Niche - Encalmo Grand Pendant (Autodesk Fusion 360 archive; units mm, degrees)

design "Encalmo Grand" references "Luxe Single Pendant Cordset - 4ft Standard", "Niche - Chief Architect - Luxe Single Pendant Cordset", "Encalmo Grand"
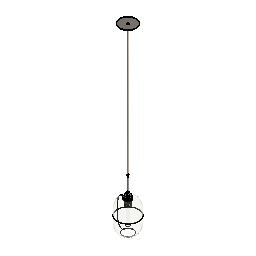
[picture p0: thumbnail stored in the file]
external_derived "ExternalDerived1" bodies "Encalmo Grand", "Encalmo Grand (1)"
external_derived "ExternalDerived2" bodies "Socket Body", "Shade Ring", "Shade Ring +Collar", "Socket", "Body1", "Metal Strain Relief", "Fabric Cord (1)", "Stem (Threaded)"
move "Move1"
external_derived "ExternalDerived3" bodies "T9-Bulb"
move "Move2"
scale "Scale1"
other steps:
derived_base_feature "Derived Base Feature1" bodies "Encalmo Grand", "Encalmo Grand (1)"
derived_base_feature "Derived Base Feature2" bodies "Socket Body", "Shade Ring", "Shade Ring +Collar", "Socket", "Body1", "Metal Strain Relief", "Fabric Cord (1)", "Stem (Threaded)"
derived_base_feature "Derived Base Feature3" bodies "T9-Bulb"
named bodies: "Encalmo Grand", "Encalmo Grand (1)", "Socket Body", "Shade Ring", "Shade Ring +Collar", "Socket", "Body1", "Metal Strain Relief", "Fabric Cord (1)", "Stem (Threaded)", "Cap (Threaded)", "5M Set Screw", "T9-Bulb"

design "Luxe Single Pendant Cordset - 4ft Standard" references "Luxe Canopy - Single Pendant Cordset"
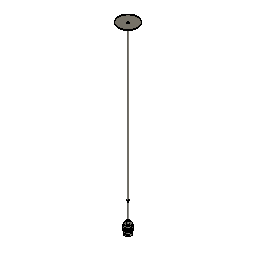
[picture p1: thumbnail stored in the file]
external_derived "ExternalDerived2" bodies "Cap (Threaded)"
move "Move1"
move "Move2"
offset_faces "OffsetFaces1" distance 1051.56
move "Move3"
move "Move4"
move "Move5"
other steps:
derived_base_feature "Derived Base Feature9" bodies "Socket Body", "Shade Ring", "Shade Ring +Collar", "Socket"
derived_base_feature "Derived Base Feature10" bodies "Body1"
derived_base_feature "Derived Base Feature12" bodies "Metal Strain Relief"
derived_base_feature "Derived Base Feature13" bodies "Fabric Cord (1)"
derived_base_feature "Derived Base Feature14" bodies "Stem (Threaded)"
derived_base_feature "Derived Base Feature15" bodies "Cap 9Threaded)", "Cap (Threaded)"
named bodies: "Socket Body", "Shade Ring", "Shade Ring +Collar", "Socket", "Metal Strain Relief", "Fabric Cord (1)", "Stem (Threaded)", "Cap 9Threaded)", "Body1", "Cap (Threaded)", "5M Set Screw"

design "Encalmo Grand" references "Niche_Encalmo_Grand_Single_Pendant"
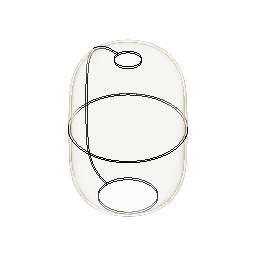
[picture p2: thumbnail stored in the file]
external_derived "ExternalDerived1" bodies "Encalmo Grand"
work_plane "WorkPlane1" AlongDistance -124.2212
split "Split1" bodies "Encalmo Grand (1)"
fillet "Fillet1" radius 0.0254
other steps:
derived_base_feature "Derived Base Feature" bodies "Encalmo Grand"
named bodies: "Encalmo Grand", "Encalmo Grand (1)"

design "Luxe Canopy - Single Pendant Cordset" references "Luxe Cordset", "M5 Set Screw", "Canopy Mounting Bar", "Plastic Strain Relief", "Canopy Mounting Bar Screw"
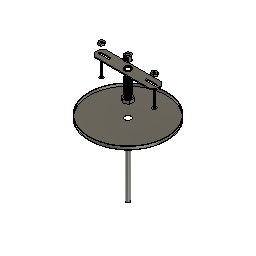
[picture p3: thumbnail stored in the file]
sketch "Sketch1" plane through (0, 0, 0) normal (0, 0, 1) x axis (1, 0, 0)
  circle C1 centre (0, 0) radius 63.5
  point P1 (0, 0)
  point P2 (0, 0)
  coincident P1 P2
  dimension "d1" diameter C1 = 127
extrude "Extrude1" new body sketch "Sketch1" along normal blind 5.08
shell "Shell1" innerThickness 0.762
hole "Hole1" HoleDepth 35.56 HoleDiameter 10.16 TipAngle 118
component_from_bodies "Body->Comp1"
component_insert "Component Insert1"
component_insert "Component Insert2"
component_insert "Component Insert3"
sketch "Sketch2" plane through (0, 0, 0) normal (0, 0, 1) x axis (1, 0, 0)
  circle C1 centre (0, 0) radius 3.175
  point P1 (0, 0)
  point P2 (0, 0)
  coincident P1 P2
  dimension "d8" diameter C1 = 6.35
extrude "Extrude2" new body sketch "Sketch2" along normal blind 127 and against normal blind 127 bodies "Fabric Cord"
component_insert "Component Insert4"
component_insert "Component Insert5"
position "Position1"
sketch "Sketch3" plane through (0, 0, 0.762) normal (0, 0, 1) x axis (-1, 0, 0)
  circle C1 centre (-0.0475, 0.2257) radius 5.08
  circle C2 centre (0, 0) radius 62.738
  circle C3 centre (0, 0) radius 4.826
  concentric C2 C3
  dimension "d13" diameter C3 = 9.652
extrude "Extrude3" new body sketch "Sketch3" profile of C3 along normal blind 25.4 bodies "Threaded Nipple"
shell "Shell2" innerThickness 1.27
thread "Thread1"
sketch "Sketch5" plane through (0, 0, 127) normal (0, 0, 1) x axis (-1, 0, 0)
  line L1 (-6.8191, 3.937) -> (0, 7.874)
  line L2 (-6.8191, -3.937) -> (-6.8191, 3.937)
  line L3 (0, -7.874) -> (-6.8191, -3.937)
  line L4 (6.8191, -3.937) -> (0, -7.874)
  line L5 (6.8191, 3.937) -> (6.8191, -3.937)
  line L6 (0, 7.874) -> (6.8191, 3.937)
  circle C1 centre (0, 0) radius 3.175
  point P2 (0, 0)
  point P9 (0, 0)
  point P3 (0, 7.874)
  coincident P2 P9
  dimension "d20" distance P3 P9 = 7.874
extrude "Extrude4" new body sketch "Sketch5" along normal blind 5.08 bodies "Hex Nut"
move "Move1"
thread "Thread2"
move "Move2" TranslateX 0 TranslateY 0 TranslateZ -55.88
move "Move3" TranslateX 0 TranslateY 0 TranslateZ 60.96
position "Position2"
sketch "Sketch6" plane through (0, 0, 0) normal (0, 0, 1) x axis (1, 0, 0)
  circle C1 centre (0, 0) radius 9.525
  point P1 (0, 0)
  point P2 (0, 0)
  coincident P1 P2
  dimension "d29" diameter C1 = 19.05
extrude "Extrude5" new body sketch "Sketch6" along normal blind 16.129 bodies "Metal Strain Relief"
move "Move4" TranslateX 0 TranslateY 0 TranslateZ -86.36
hole "Hole2" HoleDepth 10.16 HoleDiameter 5.08 TipAngle 118
hole "Hole3" HoleDepth 4.064 HoleDiameter 7.62 TipAngle 180
hole "Hole4" HoleDepth 12.192 HoleDiameter 9.144 TipAngle 180
thread "Thread3" ThreadOffset 0 ThreadLength 6.096
move "Move1" TranslateX 0 TranslateY 0 TranslateZ 68.58
move "Move5" TranslateX 0 TranslateY 0 TranslateZ 138.43
component_insert "Component Insert6"
external_derived "ExternalDerived1" bodies "5M Set Screw"
move "Move6" TranslateX 0 TranslateY 0 TranslateZ -185.42
copy_paste_bodies "CopyPasteBodies1"
move "Move7" TranslateX 0 TranslateY 0 TranslateZ -12.7
offset_faces "OffsetFaces1" distance -152.4
move "Move8"
component_from_bodies "Body->Comp2"
component_from_bodies "Body->Comp3"
component_from_bodies "Body->Comp4"
component_from_bodies "Body->Comp5"
hole "Hole1" HoleDepth 25.4 HoleDiameter 6.35 TipAngle 180
sketch "Sketch7" plane through (0, 0, 0) normal (0, 0, 1) x axis (1, 0, 0)
  line L1 (49.784, 3.9595) -> (52.07, 0)
  line L2 (45.212, 3.9595) -> (49.784, 3.9595)
  line L3 (42.926, 0) -> (45.212, 3.9595)
  line L4 (45.212, -3.9595) -> (42.926, 0)
  line L5 (49.784, -3.9595) -> (45.212, -3.9595)
  line L6 (52.07, 0) -> (49.784, -3.9595)
  point P2 (52.07, 0)
  point P8 (47.498, 0)
  dimension "d63" distance P2 P8 = 4.572
extrude "Extrude6" new body sketch "Sketch7" along normal blind 3.175 bodies "Mounting Hex Nut"
hole "Hole5" HoleDepth 25.4 HoleDiameter 3.81 TipAngle 180
thread "Thread4"
move "Move9"
component_from_bodies "Body->Comp6"
copy_paste "CopyPaste1"
move "Move10"
derived_base_feature "Derived Base Feature3" bodies "Stem (Threaded)", "Cap 9Threaded)"
move "Move11"
component_from_bodies "Body->Comp7"
component_from_bodies "Body->Comp8"
component_from_bodies "Body->Comp9"
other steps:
base_feature "Base Feature1"
base_feature "Base Feature1" bodies "Stem (Threaded)"
base_feature "Base Feature1" bodies "Cap 9Threaded)"
base_feature "Base Feature1" bodies "Fabric Cord"
base_feature "Base Feature1" bodies "Metal Strain Relief"
base_feature "Base Feature1" bodies "Mounting Hex Nut"
base_feature "Base Feature1" bodies "Hex Nut"
base_feature "Base Feature1" bodies "Fabric Cord (1)"
base_feature "Base Feature1" bodies "Threaded Nipple"
derived_base_feature "Derived Base Feature1" bodies "Socket Body", "Shade Ring", "Shade Ring +Collar", "Socket", "Rigid Stem"
derived_base_feature "Derived Base Feature2" bodies "5M Set Screw"
base_feature "Base Feature1" bodies "Fabric Cord", "Fabric Cord (1)"
create_component "CreateComponent1"
remove_body "RemoveBody1"
create_component "CreateComponent2"
remove_body "RemoveBody2"
create_component "CreateComponent3"
remove_body "RemoveBody3"
create_component "CreateComponent4"
remove_body "RemoveBody4"
create_component "CreateComponent5"
remove_body "RemoveBody5"
create_component "CreateComponent6"
remove_body "RemoveBody6"
create_component "CreateComponent7"
remove_body "RemoveBody7"
create_component "CreateComponent8"
remove_body "RemoveBody8"
create_component "CreateComponent9"
remove_body "RemoveBody9"
named bodies: "Fabric Cord", "Threaded Nipple", "Hex Nut", "Metal Strain Relief", "Socket Body", "Shade Ring", "Shade Ring +Collar", "Socket", "Rigid Stem", "5M Set Screw", "Fabric Cord (1)", "Mounting Hex Nut", "Stem (Threaded)", "Cap 9Threaded)"

design "Niche - Chief Architect - Luxe Single Pendant Cordset"
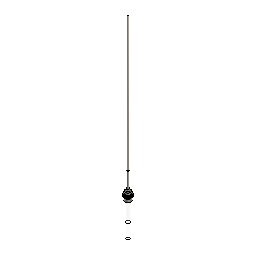
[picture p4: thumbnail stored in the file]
derived_base_feature "Derived Base Feature" bodies "Socket Body", "Shade Ring", "Shade Ring +Collar", "Socket", "Canopy", "Metal Strain Relief", "Fabric Cord (1)", "Stem (Threaded)"
remove_body "RemoveBody1"
remove_body "RemoveBody2"
split "Split1" bodies "Socket Body (1)"
remove_body "RemoveBody3"
align "Align1"
hole "Hole1" HoleDepth 19.05 HoleDiameter 8.89 TipAngle 118
combine "Combine1" bodies "Shade Ring"
split "Split2" bodies "Socket (1)"
remove_body "RemoveBody4"
split "Split3" bodies "Fabric Cord (1) (1)"
remove_body "RemoveBody5"
combine "Combine2" bodies "Socket Body"
align "Align2"
combine "Combine3" bodies "Metal Strain Relief"
sketch "Sketch1" plane through (0, 0, 0) normal (0, 1, 0) x axis (1, 0, 0)
  line L1 (13.1098, 24.9049) -> (-12.2902, 24.9049)
  line L2 (18.1898, 37.1766) -> (18.1898, 29.9849)
  line L3 (-17.3702, 29.9849) -> (-17.3702, 36.7132)
  line L4 (0, 132.969) -> (0, 24.9049)
  arc A1 centre (0, 86.36) radius 46.609 clockwise from (-22.6031, 45.5985) to (23.276, 45.979)
  arc A2 centre (-27.5302, 36.7132) radius 10.16 clockwise from (-22.6031, 45.5985) to (-17.3702, 36.7132)
  arc A3 centre (28.3498, 37.1766) radius 10.16 clockwise from (18.1898, 37.1766) to (23.276, 45.979)
  arc A4 centre (-12.2902, 29.9849) radius 5.08 clockwise from (-12.2902, 24.9049) to (-17.3702, 29.9849)
  arc A5 centre (13.1098, 29.9849) radius 5.08 clockwise from (18.1898, 29.9849) to (13.1098, 24.9049)
  point P5 (18.1898, 43.4469)
  point P3 (-17.3702, 24.9049)
  point P4 (18.1898, 24.9049)
  point P18 (0, 24.9049)
  point P19 (0, 132.969)
  horizontal L1
  vertical L2
  vertical L3
  tangent A1 A2
  tangent L3 A2
  coincident P5 L2
  coincident P5 A1
  tangent L2 A3
  tangent A1 A3
  equal A2 A3
  coincident P3 L1
  coincident P3 L3
  tangent L1 A4
  tangent L3 A4
  coincident P4 L1
  coincident P4 L2
  tangent L1 A5
  tangent L2 A5
  coincident L1 P18
  coincident A1 P19
  perpendicular L1 L4
  dimension "d4" diameter A1 = 93.218
  dimension "d5" distance P3 P4 = 35.56
  dimension "d6" distance P4 P5 = 18.542
  dimension "d7" radius A2 = 10.16
  dimension "d8" radius A4 = 5.08
  dimension "d9" radius A5 = 5.08
revolve "Revolve1" sketch "Sketch1" AlongAngle 360 bodies "G30-Bulb"
move "Move1"
sketch "Sketch2" plane through (0, 0, 0) normal (0, 1, 0) x axis (1, 0, 0)
  line L1 (12.7, 0) -> (-12.7, 0)
  line L2 (12.7, 152.4) -> (12.7, 0)
  line L3 (-12.7, 0) -> (-12.7, 152.4)
  line L4 (0, 165.1) -> (0, 0)
  arc A1 centre (0, 152.4) radius 12.7 clockwise from (-12.7, 152.4) to (12.7, 152.4)
  point P1 (0, 0)
  point P7 (0, 0)
  point P8 (0, 165.1)
  horizontal L1
  vertical L2
  vertical L3
  coincident P1 P7
  midpoint A1 P8
  perpendicular L1 L4
revolve "Revolve2" sketch "Sketch2" AlongAngle 360 bodies "T9-Bulb"
move "Move2"
sketch "Sketch3" plane through (0, 0, 0) normal (0, 1, 0) x axis (1, 0, 0)
  line L1 (12.7, 0) -> (-12.7, 0)
  line L2 (12.7, 254) -> (12.7, 0)
  line L3 (-12.7, 0) -> (-12.7, 254)
  line L4 (0, 266.7) -> (0, 0)
  arc A1 centre (0, 254) radius 12.7 clockwise from (-12.7, 254) to (12.7, 254)
  point P1 (0, 0)
  point P7 (0, 0)
  point P8 (0, 266.7)
  horizontal L1
  vertical L2
  vertical L3
  coincident P1 P7
  midpoint A1 P8
  perpendicular L1 L4
revolve "Revolve3" sketch "Sketch3" AlongAngle 360 bodies "T8-Bulb"
move "Move3"
move "Move4"
move "Move5"
sketch "Sketch4" plane through (0, 0, 0) normal (0, 1, 0) x axis (1, 0, 0)
  line L1 (15.875, -8.763) -> (-15.875, -8.763)
  line L2 (15.875, 22.987) -> (15.875, -8.763)
  line L3 (-15.875, 22.987) -> (15.875, 22.987)
  line L4 (-15.875, -8.763) -> (-15.875, 22.987)
  line L5 (0, 22.987) -> (0, -8.763)
  point P6 (0, -8.763)
  point P7 (0, 22.987)
  point P2 (-15.875, -8.763)
  point P3 (15.875, -8.763)
  point P5 (-15.875, 22.987)
  horizontal L1
  vertical L2
  horizontal L3
  vertical L4
  midpoint L1 P6
  midpoint L3 P7
  dimension "d13" distance P2 P3 = 31.75
  dimension "d14" distance P2 P5 = 31.75
revolve "Revolve4" sketch "Sketch4" AlongAngle 360 bodies "Bulb Extender"
move "Move6"
sketch "Sketch5" plane through (0, 0, 0) normal (0, 1, 0) x axis (1, 0, 0)
  line L1 (-12.7, 35.56) -> (12.7, 35.56)
  line L2 (-12.7, 5.08) -> (-12.7, 35.56)
  line L3 (12.7, 5.08) -> (-12.7, 5.08)
  line L4 (12.7, 35.56) -> (12.7, 5.08)
  line L5 (-12.7, 5.08) -> (12.7, 35.56)
  line L6 (12.7, 5.08) -> (-12.7, 35.56)
  line L7 (0, 35.56) -> (0, 5.08)
  point P6 (0, 20.32)
  point P7 (0, 5.08)
  point P8 (0, 35.56)
  horizontal L1
  perpendicular L1 L2
  parallel L1 L3
  parallel L2 L4
  coincident L5 P6
  coincident L6 P6
  midpoint L3 P7
  midpoint L1 P8
revolve "Revolve5" sketch "Sketch5" AlongAngle 360 bodies "Y-Spliter"
sketch "Sketch6" plane through (0, 0, 0) normal (0, 1, 0) x axis (1, 0, 0)
  line L1 (-55.88, 64.9514) -> (-21.59, 64.9514)
  line L2 (-55.88, 35.7414) -> (-55.88, 64.9514)
  line L3 (-21.59, 35.7414) -> (-55.88, 35.7414)
  line L4 (-21.59, 64.9514) -> (-21.59, 35.7414)
  line L5 (-55.88, 35.7414) -> (-21.59, 64.9514)
  line L6 (-21.59, 35.7414) -> (-55.88, 64.9514)
  line L7 (-38.735, 64.9514) -> (-38.735, 35.7414)
  point P6 (-38.735, 50.3464)
  point P7 (-38.735, 35.7414)
  point P8 (-38.735, 64.9514)
  point P4 (-55.88, 35.7414)
  point P5 (-21.59, 35.7414)
  point P2 (-21.59, 64.9514)
  horizontal L1
  perpendicular L1 L2
  parallel L1 L3
  parallel L2 L4
  coincident L5 P6
  coincident L6 P6
  midpoint L3 P7
  midpoint L1 P8
  dimension "d17" distance P4 P5 = 34.29
  dimension "d18" distance P2 P5 = 29.21
revolve "Revolve6" sketch "Sketch6" AlongAngle 360
chamfer "Chamfer1" distance 7.62
move "Move7"
mirror "Mirror1" mirrorStitchTolerance 0.1016
move "Move8"
combine "Combine4"
move "Move9"
sketch "Sketch7" plane through (0, 0, 0) normal (0, 1, 0) x axis (1, 0, 0)
  line L1 (-15.24, 40.64) -> (-15.24, 48.1816)
  line L2 (12.7, 38.1) -> (-12.7, 38.1)
  line L3 (15.24, 48.1816) -> (15.24, 40.64)
  line L4 (0, 100.1623) -> (0, 38.1)
  arc A1 centre (0, 76.2) radius 23.9623 clockwise from (-19.7282, 62.5988) to (19.7282, 62.5988)
  arc A2 centre (-40.64, 48.1816) radius 25.4 clockwise from (-19.7282, 62.5988) to (-15.24, 48.1816)
  arc A3 centre (40.64, 48.1816) radius 25.4 clockwise from (15.24, 48.1816) to (19.7282, 62.5988)
  arc A4 centre (-12.7, 40.64) radius 2.54 clockwise from (-12.7, 38.1) to (-15.24, 40.64)
  arc A5 centre (12.7, 40.64) radius 2.54 clockwise from (15.24, 40.64) to (12.7, 38.1)
  point P15 (0, 38.1)
  point P16 (0, 100.1623)
  parallel L1 L3
  tangent A1 A2
  tangent L1 A2
  tangent A1 A3
  tangent L3 A3
  tangent L1 A4
  tangent L2 A4
  tangent L2 A5
  tangent L3 A5
  midpoint L2 P15
  midpoint A1 P16
  perpendicular L2 L4
  dimension "d23" radius A2 = 25.4
  dimension "d24" radius A3 = 25.4
  dimension "d25" radius A4 = 2.54
  dimension "d26" radius A5 = 2.54
revolve "Revolve7" sketch "Sketch7" AlongAngle 360 bodies "A15-Bulb"
move "Move10"
copy_paste_bodies "CopyPasteBodies1"
copy_paste_bodies "CopyPasteBodies2"
move "Move11"
mirror "Mirror2" mirrorStitchTolerance 0.1016 bodies "A15-Bulb (1) (1)"
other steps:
base_feature "Base Feature1" bodies "Y-Spliter", "Bulb Extender", "Y-Spliter (1)", "Bulb Extender (1)"
base_feature "Base Feature2" bodies "A15-Bulb", "A15-Bulb (1)"
named bodies: "Socket Body", "Shade Ring", "Shade Ring +Collar", "Socket", "Canopy", "Metal Strain Relief", "Fabric Cord (1)", "Stem (Threaded)", "Adapter", "5M Set Screw", "Body1 (1)", "Socket Body (1)", "Socket (1)", "Fabric Cord (1) (1)", "G30-Bulb", "T9-Bulb", "T8-Bulb", "Bulb Extender", "Y-Spliter", "A15-Bulb", "Y-Spliter (1)", "Bulb Extender (1)", "A15-Bulb (1)", "A15-Bulb (1) (1)"

design "M5 Set Screw"
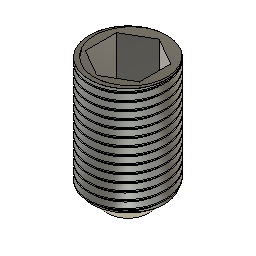
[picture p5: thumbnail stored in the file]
sketch "Sketch1" plane through (0, 0, 0) normal (0, 0, 1) x axis (1, 0, 0)
  circle C1 centre (0, 0) radius 2.5
  point P1 (0, 0)
  point P2 (0, 0)
  coincident P1 P2
  dimension "d1" diameter C1 = 5
extrude "Extrude1" new body sketch "Sketch1" along normal blind 8
sketch "Sketch2" plane through (0, 0, 8) normal (0, 0, 1) x axis (-1, 0, 0)
  line L1 (-1.7321, 1) -> (0, 2)
  line L2 (-1.7321, -1) -> (-1.7321, 1)
  line L3 (0, -2) -> (-1.7321, -1)
  line L4 (1.7321, -1) -> (0, -2)
  line L5 (1.7321, 1) -> (1.7321, -1)
  line L6 (0, 2) -> (1.7321, 1)
  circle C1 centre (0, 0) radius 2.5
  point P2 (0, 0)
  point P9 (0, 0)
  coincident P2 P9
extrude "Extrude2" cut sketch "Sketch2" profile of L1 L2 L3 L4 L5 L6 against normal blind 3
thread "Thread1" ThreadOffset 0.99 ThreadLength 7
chamfer "Chamfer1" distance 1.15

design "Luxe Cordset" references "M5 Set Screw"
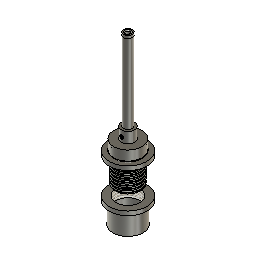
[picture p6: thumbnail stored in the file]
sketch "Sketch1" plane through (0, 0, 0) normal (0, 0, 1) x axis (1, 0, 0)
  circle C1 centre (0, 0) radius 20.6
  point P1 (0, 0)
  point P2 (0, 0)
  coincident P1 P2
  dimension "d11" diameter C1 = 41.2
extrude "Extrude1" new body sketch "Sketch1" along normal blind 14 bodies "Socket Body"
sketch "Sketch2" plane through (0, 0, 14) normal (0, 0, 1) x axis (-1, 0, 0)
  circle C1 centre (0, 0) radius 20.6
  circle C2 centre (0, 0) radius 9.6
  concentric C1 C2
  dimension "d3" diameter C2 = 19.2
extrude "Extrude2" add sketch "Sketch2" profile of C2 along normal blind 15.75
sketch "Sketch3" plane through (0, 0, 29.75) normal (0, 0, 1) x axis (-1, 0, 0)
  circle C1 centre (0, 0) radius 9.6
  circle C2 centre (0, 0) radius 5.75
  concentric C1 C2
  dimension "d6" diameter C2 = 11.5
extrude "Extrude3" new body sketch "Sketch3" profile of C2 along normal blind 114 bodies "Rigid Stem"
move "Move1"
sketch "Sketch4" plane through (0, 0, 203.75) normal (0, 0, 1) x axis (-1, 0, 0)
  circle C1 centre (0, 0) radius 5.75
  circle C2 centre (0, 0) radius 27.5
  dimension "d10" diameter C2 = 55
extrude "Extrude4" new body sketch "Sketch4" profile of C2 along normal blind 6 bodies "Shade Ring"
hole "Hole1" HoleDepth 25 HoleDiameter 42.75 TipAngle 118
sketch "Sketch5" plane through (0, 0, 0) normal (0, 0, 1) x axis (1, 0, 0)
  circle C1 centre (0, 0) radius 22
  point P1 (0, 0)
  point P2 (0, 0)
  coincident P1 P2
  dimension "d18" diameter C1 = 44
move "Move2"
copy_paste_bodies "CopyPasteBodies1"
move "Move3"
sketch "Sketch6" plane through (0, 0, 60) normal (0, 0, -1) x axis (1, 0, 0)
  circle C1 centre (0, 0) radius 20.6
  circle C2 centre (0, 0) radius 21.375
  circle C3 centre (0, 0) radius 20
  concentric C1 C2
  concentric C1 C3
  dimension "d21" diameter C2 = 42.75
  dimension "d24" diameter C3 = 40
cylinder_primitive "CylinderPrimitive1" Height 8 Diameter 42.75
thread "Thread1"
thread "Thread3"
hole "Hole2" HoleDepth 18 HoleDiameter 39 TipAngle 180
move "Move4"
move "Move5"
move "Move6"
hole "Hole3" HoleDepth 114 HoleDiameter 7.6 TipAngle 180
derived_base_feature "Derived Base Feature" bodies "Socket"
move "Move7"
scale "Scale1" ScaleX 1.2 ScaleY 1.2
move "Move8"
sketch "Sketch8" plane through (0, 0, -23.9827) normal (0, 0, -1) x axis (1, 0, 0)
  circle C1 centre (0, -0.036) radius 27.5
  circle C2 centre (0, -0.036) radius 22
  circle C3 centre (0, -0.036) radius 19.5
  dimension "d36" diameter C2 = 44
  dimension "d42" = -2.5
extrude "Extrude7" add sketch "Sketch8" profile of C2 C3 along normal blind 30
offset_faces "OffsetFaces1" distance 2.75
offset_faces "OffsetFaces2" distance -9
thread "Thread2"
move "Move9"
move "Move10"
move "Move11"
scale "Scale2" ScaleZ 1.2
move "Move12"
move "Move13"
move "Move14"
move "Move15"
move "Move16"
split_face "SplitFace1"
move "Move17"
move "Move18"
move "Move19"
move "Move20"
move "Move21"
move "Move22"
move "Move23"
move "Move24"
move "Move25"
move "Move26"
move "Move27"
thread "Thread4"
move "Move28"
move "Move29"
move "Move30"
hole "Hole4" HoleDepth 21 HoleDiameter 39.35 TipAngle 180
hole "Hole5" HoleDepth 9 HoleDiameter 5 TipAngle 180
move "Move31"
move "Move32"
hole "Hole6" HoleDepth 20 HoleDiameter 10 TipAngle 180
move_face "MoveFace3"
move "Move33"
move "Move34"
move "Move35"
move "Move36"
move "Move37"
thread "Thread5" ThreadOffset 0 ThreadLength 6
thread "Thread6" ThreadOffset 0 ThreadLength 6
move "Move38"
move "Move39"
move "Move40"
move "Move41"
component_insert "Component Insert"
thread "Thread7" ThreadOffset 0.5 ThreadLength 5.337
chamfer "Chamfer1" distance 0.5 distance 0.35
sketch "Sketch12" plane through (0, 0, 0) normal (0, 0, 1) x axis (1, 0, 0)
  circle C1 centre (0, 0) radius 6.35
  dimension "d60" diameter C1 = 12.7
extrude "Extrude8" new body sketch "Sketch12" along normal blind 115 bodies "Stem (Threaded)"
hole "Hole7" HoleDepth 115 HoleDiameter 9.65 TipAngle 118
thread "Thread8" ThreadOffset 0 ThreadLength 12.5
thread "Thread9" ThreadOffset 0 ThreadLength 12.5
sketch "Sketch13" plane through (0, 0, 0) normal (0, 0, 1) x axis (1, 0, 0)
  circle C1 centre (0, 0) radius 6.35
  point P1 (0, 0)
  point P2 (0, 0)
  coincident P1 P2
  dimension "d70" diameter C1 = 12.7
extrude "Extrude9" new body sketch "Sketch13" along normal blind 4 bodies "Cap 9Threaded)"
sketch "Sketch14" plane through (0, 0, 4) normal (0, 0, 1) x axis (-1, 0, 0)
  circle C1 centre (0, 0) radius 6.35
  circle C2 centre (0, 0) radius 4.5
  concentric C1 C2
  dimension "d73" diameter C2 = 9
extrude "Extrude10" add sketch "Sketch14" profile of C2 against normal blind 14
thread "Thread10"
hole "Hole8" HoleDepth 115 HoleDiameter 6.5 TipAngle 118 CSDiameter 9 CSAngle 90
move "Move42"
move "Move43"
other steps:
base_feature "Base Feature" bodies "Shade Ring +Collar"
named bodies: "Socket Body", "Shade Ring", "Shade Ring +Collar", "Socket", "Rigid Stem", "Stem (Threaded)", "Cap 9Threaded)"

design "Plastic Strain Relief"
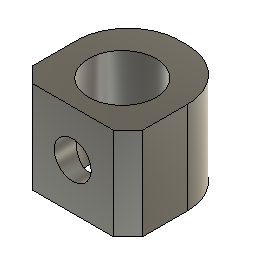
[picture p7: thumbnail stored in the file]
base_feature "Base Feature" bodies "strainrelief"
named bodies: "strainrelief"

design "Canopy Mounting Bar Screw"
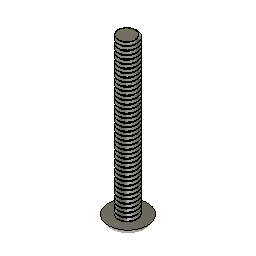
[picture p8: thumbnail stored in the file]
base_feature "Base Feature" bodies "screw1"
named bodies: "screw1"

design "Canopy Mounting Bar"
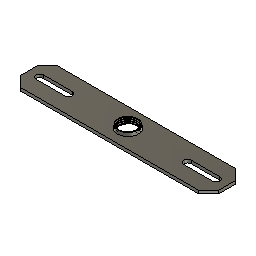
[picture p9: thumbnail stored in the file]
base_feature "Base Feature" bodies "mountingbar"
named bodies: "mountingbar"

design "Niche_Encalmo_Grand_Single_Pendant"
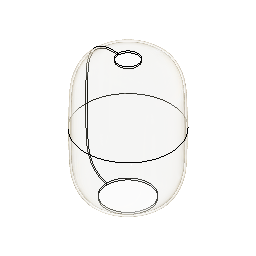
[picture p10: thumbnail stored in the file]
